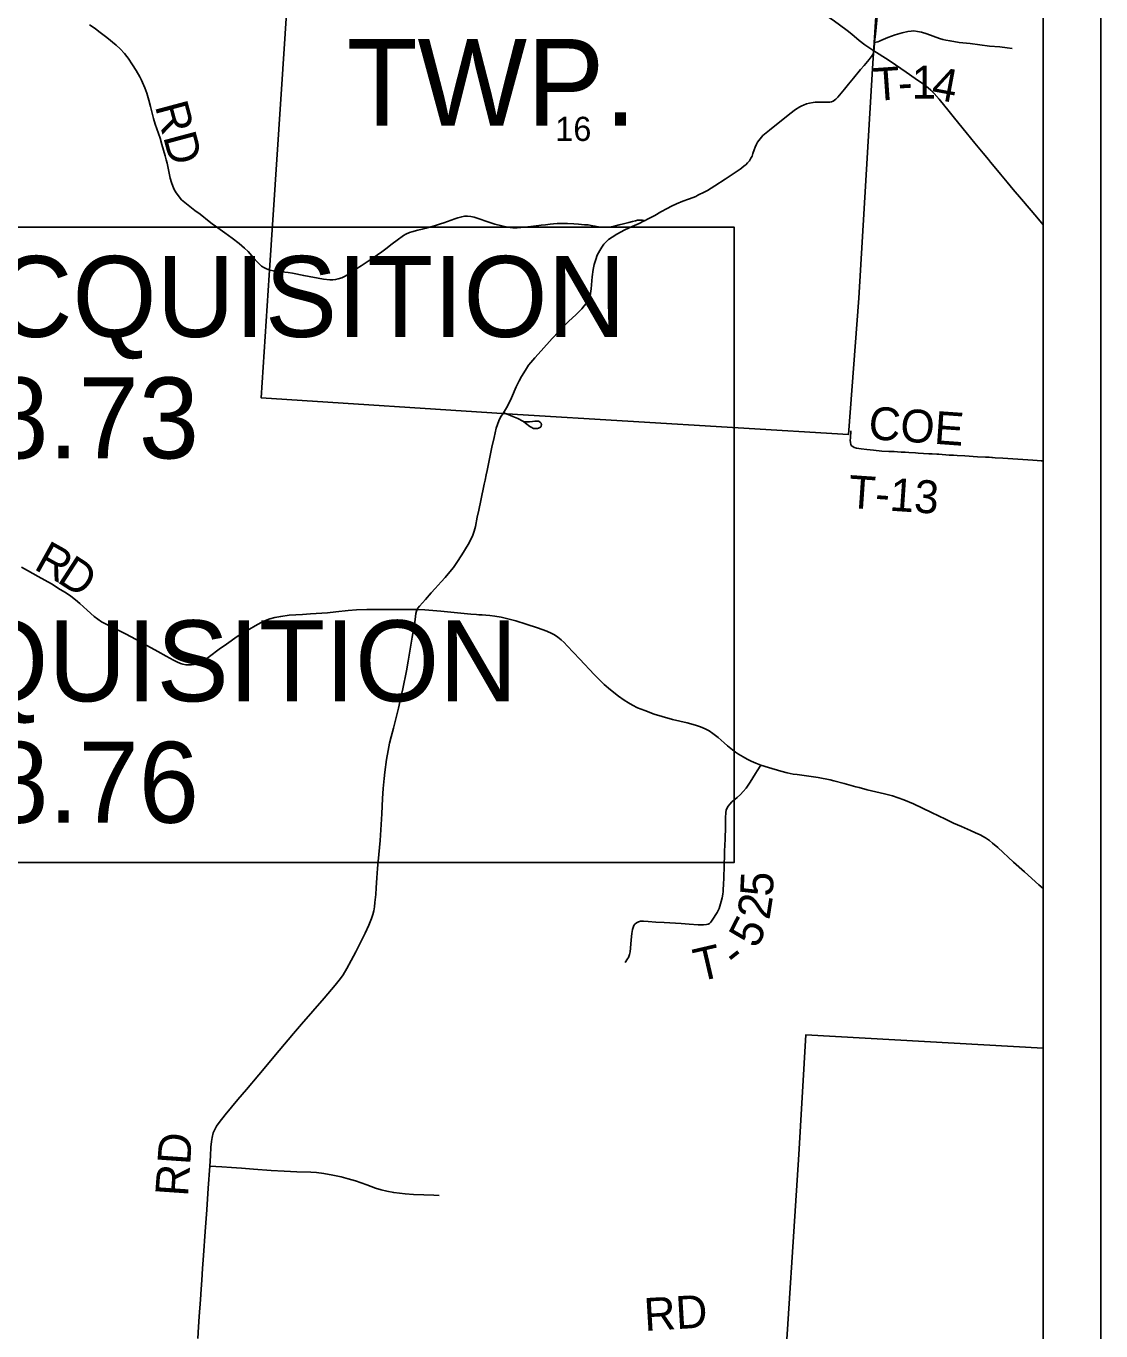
# Model space of a CAD drawing. Extents: x 0 to 34, y 0 to 22.
# Drawn here: x 7.141 to 9, y 16.952 to 19.209 of the extents above; entities that cross this region are included whole.
import ezdxf

# ---------------------------------------------------------------- set-up
doc = ezdxf.new("R2010")
doc.units = 0
for name, color, linetype in [('GM_X_Corporation', 7, 'Continuous'), ('GM_X_County_Road', 7, 'Continuous'), ('GM_X_County_Road_Text', 7, 'Continuous'), ('GM_X_Section_Text', 7, 'Continuous'), ('GM_X_State_Route', 7, 'Continuous'), ('GM_X_Township_Road', 7, 'Continuous'), ('GM_X_Township_Road_Text', 7, 'Continuous'), ('GM_X_Township_Text', 7, 'Continuous'), ('SH_Data', 7, 'Continuous'), ('SH_Text', 7, 'Continuous')]:
    doc.layers.add(name, color=color, linetype=linetype)

msp = doc.modelspace()

# ---------------------------------------------------------------- linework, layer by layer
at = {"layer": 'GM_X_Corporation'}
for points in [[(7.6147, 19.5863), (8.6299, 19.5205), (8.6049, 19.1351), (8.5816, 18.7382), (8.5636, 18.5025), (7.9912, 18.537), (7.548, 18.5656), (7.5613, 18.7776), (7.5889, 19.1863)], [(8.9, 16.3939), (8.9, 17.4412), (8.4898, 17.4646), (8.4777, 17.2575), (8.4507, 16.8404), (8.4238, 16.4246)]]:
    msp.add_lwpolyline(points, close=True, dxfattribs=at)
at = {"layer": 'GM_X_County_Road'}
for points in [[(8.6077, 19.1703), (8.6086, 19.18), (8.6087, 19.1812), (8.61, 19.1947), (8.6135, 19.231)], [(7.465, 17.2947), (7.4676, 17.3009), (7.4705, 17.3063), (7.4749, 17.313), (7.4854, 17.3261), (7.5074, 17.3524), (7.5221, 17.3696), (7.5437, 17.3949), (7.5789, 17.4371), (7.6037, 17.4665), (7.6175, 17.4825), (7.6569, 17.528), (7.6758, 17.5504), (7.6848, 17.5618), (7.6893, 17.5682), (7.6959, 17.5791), (7.7035, 17.593), (7.7114, 17.6078), (7.719, 17.6228), (7.7275, 17.6401), (7.734, 17.6542), (7.7386, 17.6657), (7.7408, 17.6723), (7.7425, 17.679), (7.7436, 17.6857), (7.7444, 17.6931), (7.7458, 17.7071), (7.7465, 17.7185), (7.7478, 17.7356), (7.7491, 17.7522), (7.7512, 17.7764), (7.7533, 17.8003), (7.7545, 17.819), (7.7562, 17.8462), (7.7577, 17.8731), (7.7588, 17.8902), (7.7593, 17.896), (7.7602, 17.9075), (7.7614, 17.9186), (7.7645, 17.9404), (7.7672, 17.9557), (7.7698, 17.9687), (7.7725, 17.9796), (7.7764, 17.9946), (7.7813, 18.0132), (7.7852, 18.0289), (7.7883, 18.0422), (7.7928, 18.0628), (7.7988, 18.0939), (7.8019, 18.1104), (7.8062, 18.1349), (7.8091, 18.1521), (7.8117, 18.1674), (7.8123, 18.1704), (7.8142, 18.1826), (7.8155, 18.1931), (7.8162, 18.1968), (7.8173, 18.1997), (7.8188, 18.2023), (7.8217, 18.2055), (7.832, 18.2171), (7.8418, 18.2284), (7.8485, 18.2358), (7.8592, 18.2478), (7.8659, 18.2552), (7.874, 18.2646), (7.8801, 18.2724), (7.8863, 18.281), (7.8947, 18.294), (7.9057, 18.312), (7.9104, 18.3208), (7.9137, 18.3282), (7.9162, 18.3352), (7.9184, 18.3435), (7.9215, 18.3592), (7.9244, 18.3717), (7.9277, 18.3881), (7.9335, 18.4163), (7.935, 18.4236), (7.9369, 18.4327), (7.9384, 18.44), (7.9444, 18.4691), (7.9467, 18.4802), (7.9505, 18.4974), (7.9543, 18.5131), (7.9562, 18.5197), (7.9587, 18.526), (7.9618, 18.5321), (7.967, 18.5399), (7.9722, 18.5487), (7.9761, 18.556), (7.9806, 18.5656), (7.9887, 18.5846), (7.9937, 18.5953), (7.9978, 18.6028), (8.0046, 18.6138), (8.0102, 18.6222), (8.0139, 18.6271), (8.0208, 18.6349), (8.0318, 18.6473), (8.051, 18.6682), (8.0625, 18.6807), (8.0801, 18.6983), (8.0917, 18.7095), (8.1021, 18.7198), (8.1065, 18.7246), (8.11, 18.729), (8.1126, 18.733), (8.1142, 18.7356), (8.1156, 18.7391), (8.1165, 18.7421), (8.1172, 18.7459), (8.1183, 18.7545), (8.1201, 18.7751), (8.122, 18.7879), (8.1239, 18.7965), (8.1263, 18.8051), (8.1291, 18.8124), (8.1333, 18.8206), (8.1367, 18.8265), (8.1405, 18.8315), (8.1441, 18.8355), (8.1487, 18.8396), (8.1546, 18.8437), (8.1628, 18.8486), (8.1769, 18.8562), (8.1894, 18.862), (8.2016, 18.8674), (8.209, 18.871), (8.2106, 18.8718), (8.2172, 18.8752), (8.2286, 18.8813), (8.2389, 18.8874), (8.2497, 18.8934), (8.2574, 18.8974), (8.2661, 18.9014), (8.2767, 18.9056), (8.2869, 18.9093), (8.2948, 18.9123), (8.2992, 18.9141), (8.3031, 18.916), (8.3066, 18.9177), (8.3116, 18.9203), (8.3195, 18.9245), (8.3326, 18.9326), (8.35, 18.9439), (8.3729, 18.9589), (8.3762, 18.9611), (8.3786, 18.9629), (8.3833, 18.9667), (8.3857, 18.9687), (8.3889, 18.9719), (8.392, 18.9756), (8.3948, 18.9801), (8.3966, 18.9837), (8.3982, 18.988), (8.4006, 18.9948), (8.4023, 18.9993), (8.4046, 19.0046), (8.4063, 19.0077), (8.4082, 19.0106), (8.4128, 19.0165), (8.4153, 19.0192), (8.418, 19.0216), (8.4268, 19.0288), (8.4622, 19.0569), (8.472, 19.0642), (8.4791, 19.0688), (8.4828, 19.0707), (8.4855, 19.072), (8.4909, 19.0739), (8.4959, 19.0752), (8.5024, 19.0764), (8.506, 19.0768), (8.5103, 19.0771), (8.5196, 19.0768), (8.5264, 19.0767), (8.5312, 19.0772), (8.534, 19.0778), (8.5368, 19.0789), (8.5393, 19.0802), (8.5418, 19.0823), (8.545, 19.0855), (8.5566, 19.0995), (8.5634, 19.1079), (8.5722, 19.1186), (8.5843, 19.1335), (8.5906, 19.1406), (8.5992, 19.1509), (8.6043, 19.1579), (8.606, 19.1608), (8.6068, 19.163), (8.6071, 19.1656)], [(8.6071, 19.1656), (8.6076, 19.1693), (8.6077, 19.1703)], [(7.133, 18.2731), (7.1434, 18.2674), (7.1623, 18.2568), (7.185, 18.2439), (7.2004, 18.2345), (7.2092, 18.2292), (7.2184, 18.2228), (7.2269, 18.2163), (7.2341, 18.2101), (7.2468, 18.1987), (7.2589, 18.1878), (7.2653, 18.1828), (7.2715, 18.1787), (7.2786, 18.1747), (7.2936, 18.1672), (7.3131, 18.1576), (7.3317, 18.1477), (7.3512, 18.1367), (7.3692, 18.1269), (7.3832, 18.119), (7.3964, 18.1121), (7.4021, 18.1093), (7.4082, 18.1064), (7.4125, 18.1051), (7.4176, 18.1039), (7.4222, 18.1038), (7.4274, 18.1042), (7.4313, 18.1047), (7.4365, 18.1061), (7.4423, 18.1086), (7.4496, 18.1122), (7.4584, 18.1186), (7.4749, 18.1309), (7.4877, 18.1401), (7.5064, 18.1532), (7.5274, 18.166), (7.5375, 18.1717), (7.5476, 18.1772), (7.5553, 18.1809), (7.5629, 18.1836), (7.5712, 18.1857), (7.5815, 18.1877), (7.5963, 18.1897), (7.6195, 18.1914), (7.6328, 18.1921), (7.6625, 18.1942), (7.6767, 18.1956), (7.6983, 18.1979), (7.7125, 18.1991), (7.7305, 18.1997), (7.7479, 18.1998), (7.7659, 18.1998), (7.7969, 18.2), (7.8106, 18.1999), (7.8173, 18.1997)], [(7.8173, 18.1997), (7.8309, 18.199), (7.8377, 18.1985), (7.8587, 18.1966), (7.8816, 18.1944), (7.9101, 18.1918), (7.92, 18.191), (7.9243, 18.1907), (7.9299, 18.1903), (7.936, 18.1898), (7.9434, 18.1892), (7.9519, 18.1881), (7.9629, 18.1863), (7.9743, 18.1839), (7.9881, 18.1802), (8.0058, 18.1745), (8.0258, 18.1678), (8.0415, 18.1622), (8.0505, 18.1583), (8.0553, 18.1557), (8.0609, 18.1519), (8.0663, 18.1474), (8.0715, 18.1425), (8.077, 18.137), (8.0986, 18.1141), (8.1237, 18.0872), (8.1328, 18.0779), (8.141, 18.0703), (8.1518, 18.0609), (8.1655, 18.0501), (8.1756, 18.0428), (8.1829, 18.0381), (8.19, 18.0341), (8.1985, 18.03), (8.2112, 18.0249), (8.2275, 18.0189), (8.2412, 18.0147), (8.2593, 18.0098), (8.2846, 18.0036), (8.299, 18), (8.3078, 17.9971), (8.3156, 17.9936), (8.3226, 17.9897), (8.3287, 17.9856), (8.338, 17.9783), (8.3483, 17.9694), (8.3544, 17.9641), (8.3627, 17.9571), (8.3678, 17.9532), (8.3731, 17.9495), (8.3813, 17.9449), (8.3884, 17.9411), (8.3954, 17.9376), (8.4034, 17.9339), (8.4116, 17.9308), (8.4251, 17.9263), (8.4462, 17.9202), (8.4572, 17.9174), (8.4675, 17.9153), (8.4749, 17.9143), (8.4946, 17.9116), (8.5111, 17.9091), (8.5318, 17.9051), (8.5384, 17.9035), (8.5559, 17.8991), (8.5762, 17.8934), (8.5821, 17.8917), (8.596, 17.888), (8.6255, 17.8808), (8.6393, 17.8773), (8.6494, 17.8744), (8.6593, 17.8708), (8.6759, 17.8639), (8.6917, 17.8563), (8.7072, 17.8488), (8.7313, 17.8372), (8.7452, 17.8305), (8.7588, 17.8243), (8.7742, 17.8178), (8.7833, 17.8138), (8.7911, 17.81), (8.8002, 17.8049), (8.8073, 17.8001), (8.8126, 17.796), (8.8215, 17.7883), (8.8488, 17.7629), (8.8678, 17.7459), (8.8928, 17.7236), (8.9, 17.7171)], [(7.438, 16.939), (7.4394, 16.9594), (7.4407, 16.9774), (7.4429, 17.0067), (7.4441, 17.0245), (7.4453, 17.0399), (7.4465, 17.0604), (7.448, 17.0828), (7.4507, 17.1242), (7.4536, 17.1619), (7.4563, 17.1993), (7.459, 17.2374), (7.46, 17.255), (7.4607, 17.27), (7.4617, 17.2799), (7.4628, 17.287), (7.465, 17.2947)]]:
    msp.add_lwpolyline(points, dxfattribs=at)
at = {"layer": 'GM_X_State_Route'}
for points in [[(8.2752, 19.5469), (8.2893, 19.5197), (8.3007, 19.5001), (8.3098, 19.4841), (8.3173, 19.4708), (8.3249, 19.4584), (8.3332, 19.4467), (8.3405, 19.4375), (8.3589, 19.4148), (8.3726, 19.398), (8.3877, 19.3798), (8.4162, 19.3436), (8.4404, 19.3134), (8.4591, 19.2914), (8.4714, 19.2774), (8.4828, 19.2642), (8.4903, 19.2559), (8.4973, 19.2488), (8.5042, 19.2425), (8.5109, 19.237), (8.5199, 19.2304), (8.5393, 19.2168), (8.5589, 19.2027), (8.5612, 19.2008)], [(8.5612, 19.2008), (8.569, 19.1946), (8.5819, 19.1838), (8.5918, 19.1762), (8.6071, 19.1656), (8.6318, 19.1499), (8.6448, 19.1414), (8.6633, 19.129), (8.6789, 19.1181), (8.693, 19.1082), (8.701, 19.102), (8.7056, 19.0979), (8.7116, 19.0917), (8.7201, 19.0819), (8.7373, 19.0606), (8.7467, 19.0491), (8.7667, 19.0245), (8.7817, 19.0063), (8.7964, 18.9886), (8.8055, 18.9776), (8.8091, 18.9733), (8.8154, 18.9656), (8.8265, 18.9523), (8.8381, 18.9385), (8.8483, 18.926), (8.8629, 18.909), (8.889, 18.8781), (8.9, 18.8651)]]:
    msp.add_lwpolyline(points, dxfattribs=at)
at = {"layer": 'GM_X_Township_Road'}
for points in [[(7.251, 19.2105), (7.2606, 19.2042), (7.2671, 19.1994), (7.2809, 19.1888), (7.2871, 19.1837), (7.2905, 19.1809), (7.2972, 19.1753), (7.3041, 19.1691), (7.3112, 19.1613), (7.3155, 19.156), (7.3178, 19.153), (7.3255, 19.1418), (7.3317, 19.1318), (7.3378, 19.1209), (7.3409, 19.1148), (7.3428, 19.1109), (7.3466, 19.1017), (7.3483, 19.0971), (7.3498, 19.0924), (7.3532, 19.0805), (7.3561, 19.0697), (7.3617, 19.0487), (7.3645, 19.0392), (7.3729, 19.0145), (7.3762, 19.0038), (7.3817, 18.9841), (7.3835, 18.9775), (7.385, 18.9715), (7.3888, 18.954), (7.3906, 18.9455), (7.3926, 18.9383), (7.395, 18.9319), (7.3975, 18.926), (7.4009, 18.92), (7.4045, 18.9148), (7.4075, 18.911), (7.4101, 18.9083), (7.4129, 18.9057), (7.4241, 18.8968), (7.4332, 18.8899), (7.4423, 18.8831), (7.4576, 18.8704), (7.4631, 18.8664), (7.4687, 18.8625), (7.4851, 18.8513), (7.4977, 18.8421), (7.5099, 18.8325), (7.5192, 18.8244), (7.525, 18.8188), (7.5375, 18.8042), (7.5452, 18.7962), (7.5484, 18.7933), (7.5521, 18.791), (7.5571, 18.7886), (7.563, 18.7866), (7.569, 18.7853), (7.5777, 18.7841), (7.5885, 18.7833), (7.5945, 18.7827), (7.6019, 18.7815), (7.6213, 18.7772), (7.6555, 18.7712), (7.6666, 18.7699), (7.6714, 18.7697), (7.6765, 18.7702), (7.6807, 18.7714), (7.6872, 18.7734), (7.6917, 18.7757), (7.6972, 18.7786), (7.7023, 18.782), (7.706, 18.7844), (7.7126, 18.7889), (7.7177, 18.7923), (7.7204, 18.794), (7.7276, 18.7987), (7.7327, 18.8021), (7.7414, 18.8079), (7.7563, 18.8183), (7.7636, 18.8236), (7.7744, 18.832), (7.7829, 18.8386), (7.7937, 18.8465), (7.7979, 18.8489), (7.8044, 18.8516), (7.8084, 18.853), (7.8186, 18.8558), (7.8263, 18.8572), (7.833, 18.8589), (7.8412, 18.8613), (7.8473, 18.8631), (7.8526, 18.8646), (7.8581, 18.8666), (7.8639, 18.8686), (7.8763, 18.8728), (7.8827, 18.875), (7.8844, 18.8756), (7.8877, 18.8768), (7.8947, 18.8788), (7.8996, 18.8797), (7.9045, 18.8799), (7.9101, 18.8795), (7.9162, 18.8782), (7.925, 18.8751), (7.9379, 18.8706), (7.9521, 18.8661), (7.9641, 18.863), (7.9739, 18.861), (7.9831, 18.8598), (7.9905, 18.8596), (7.9967, 18.86), (8.0029, 18.8606), (8.014, 18.8619), (8.0281, 18.8637), (8.032, 18.8642), (8.0394, 18.8648), (8.0474, 18.8658), (8.0535, 18.8667), (8.0597, 18.8672), (8.0676, 18.8672), (8.0773, 18.8671), (8.0885, 18.8666), (8.0968, 18.8659), (8.1071, 18.8651), (8.1135, 18.8646), (8.1182, 18.864), (8.1249, 18.8627), (8.1312, 18.8614), (8.1398, 18.8607), (8.1472, 18.8609), (8.1533, 18.8616), (8.1581, 18.8624), (8.1669, 18.8646), (8.1741, 18.8665), (8.1791, 18.8679), (8.1835, 18.8691), (8.1897, 18.8707), (8.1949, 18.872), (8.1987, 18.8728), (8.203, 18.8732), (8.207, 18.8731), (8.2095, 18.8722), (8.2106, 18.8718)], [(8.6086, 19.18), (8.6144, 19.1813), (8.6171, 19.1822), (8.6195, 19.1834), (8.6316, 19.1888), (8.6439, 19.1932), (8.6564, 19.197), (8.6661, 19.1993), (8.6716, 19.2), (8.6766, 19.2001), (8.6827, 19.1994), (8.69, 19.1978), (8.6989, 19.195), (8.7211, 19.1873), (8.7265, 19.1856), (8.732, 19.1842), (8.7393, 19.1828), (8.7547, 19.1803), (8.7741, 19.1782), (8.8076, 19.1741), (8.8251, 19.1724), (8.8377, 19.171), (8.8463, 19.1697)], [(7.967, 18.5399), (7.975, 18.5369), (7.9829, 18.5337), (7.9917, 18.5299), (8, 18.5256), (8.0022, 18.5242), (8.0051, 18.5221), (8.0124, 18.5164), (8.0161, 18.5142), (8.0175, 18.5135), (8.019, 18.513), (8.0203, 18.5127), (8.0214, 18.5126), (8.0235, 18.5125), (8.0255, 18.5127), (8.0274, 18.5132), (8.0288, 18.5137), (8.0299, 18.5143), (8.0308, 18.515), (8.0312, 18.5157), (8.0318, 18.5166), (8.0322, 18.5177), (8.0323, 18.5186), (8.0323, 18.5199), (8.0322, 18.5206), (8.0317, 18.5219), (8.031, 18.5229), (8.03, 18.5239), (8.0292, 18.5245), (8.0285, 18.5249), (8.0275, 18.5252), (8.0268, 18.5254), (8.0258, 18.5255), (8.0242, 18.5255), (8.0213, 18.5252), (8.0172, 18.5247), (8.0117, 18.5243), (8.0073, 18.5242), (8.005, 18.5244), (8.0019, 18.5247)], [(8.5673, 18.5085), (8.5667, 18.496), (8.5665, 18.4924), (8.5667, 18.4884), (8.5673, 18.4849), (8.5685, 18.4829), (8.5707, 18.4814), (8.5733, 18.4799), (8.5775, 18.4786), (8.5855, 18.4775), (8.5954, 18.4764), (8.6065, 18.4751), (8.6212, 18.4738), (8.6333, 18.4732), (8.6425, 18.4727), (8.6485, 18.4725), (8.6546, 18.472), (8.6613, 18.4717), (8.668, 18.4712), (8.6791, 18.4706), (8.684, 18.4702), (8.7025, 18.4691), (8.708, 18.4689), (8.716, 18.4683), (8.7198, 18.4681), (8.7377, 18.4669), (8.7452, 18.4665), (8.7514, 18.4661), (8.7644, 18.4654), (8.7867, 18.464), (8.8003, 18.4632), (8.8065, 18.4629), (8.8114, 18.4626), (8.8126, 18.4625), (8.8169, 18.4622), (8.8303, 18.4613), (8.8562, 18.4596), (8.8823, 18.4579), (8.8897, 18.4575), (8.8965, 18.4569), (8.9, 18.4567)], [(8.1773, 17.5893), (8.1815, 17.5956), (8.1829, 17.5983), (8.1847, 17.603), (8.1859, 17.6078), (8.1867, 17.6139), (8.1878, 17.6288), (8.1888, 17.6394), (8.1902, 17.6467), (8.191, 17.6501), (8.1921, 17.6531), (8.1942, 17.6558), (8.1967, 17.658), (8.2002, 17.6598), (8.2035, 17.6609), (8.2088, 17.6609), (8.2169, 17.6605), (8.2305, 17.6593), (8.2448, 17.6584), (8.2739, 17.6567), (8.2881, 17.6558), (8.3036, 17.6548), (8.3129, 17.6546), (8.3179, 17.655), (8.3208, 17.6558), (8.323, 17.657), (8.3253, 17.6591), (8.3279, 17.6626), (8.3362, 17.6757), (8.3396, 17.683), (8.341, 17.6866), (8.3424, 17.6907), (8.3435, 17.695), (8.3449, 17.7014), (8.346, 17.7078), (8.3465, 17.7121), (8.3467, 17.7152), (8.3472, 17.7246), (8.3477, 17.735), (8.3482, 17.7569), (8.3489, 17.7758), (8.349, 17.782), (8.35, 17.8028), (8.3505, 17.8241), (8.3509, 17.8395), (8.3514, 17.849), (8.3519, 17.8527), (8.3534, 17.8567), (8.3553, 17.8599), (8.358, 17.8633), (8.362, 17.8673), (8.371, 17.8749), (8.3766, 17.8798), (8.3813, 17.8848), (8.3863, 17.8911), (8.3932, 17.9014), (8.4025, 17.9162), (8.4055, 17.921), (8.4116, 17.9308)], [(7.459, 17.2374), (7.4798, 17.2361), (7.4965, 17.2349), (7.5138, 17.2337), (7.5343, 17.2322), (7.5652, 17.23), (7.5875, 17.2287), (7.6092, 17.2276), (7.6334, 17.2268), (7.6433, 17.226), (7.6562, 17.2244), (7.6715, 17.2218), (7.6861, 17.2188), (7.6981, 17.2156), (7.7106, 17.2117), (7.7305, 17.2047), (7.7457, 17.1993), (7.7552, 17.1964), (7.7648, 17.1941), (7.777, 17.1917), (7.7967, 17.1892), (7.8109, 17.188), (7.8289, 17.1875), (7.8463, 17.1872), (7.8557, 17.1867)]]:
    msp.add_lwpolyline(points, dxfattribs=at)
at = {"layer": 'SH_Data'}
for p, q in [((9, 21), (9, 14)), ((8.9, 20.9), (8.9, 14.1))]:
    msp.add_line(p, q, dxfattribs=at)
at = {"layer": 'SH_Text'}
for points in [[(8.3656, 18.861), (6.2897, 18.861), (6.2897, 17.7622), (8.3656, 17.7622)], [(6.2897, 18.861), (8.3656, 18.861), (8.3656, 17.7622), (6.2897, 17.7622)]]:
    msp.add_lwpolyline(points, close=True, dxfattribs=at)

# ---------------------------------------------------------------- texts
at = {"layer": 'GM_X_County_Road_Text'}
for s, height, rotation, p in [('R', 0.0568, 330.9067, (7.1527, 18.2706)), ('D', 0.0568, 327.0323, (7.1927, 18.2484)), ('RD', 0.05682, 86.0551, (7.4211, 17.1838))]:
    msp.add_text(s, height=height, rotation=rotation, dxfattribs=at).set_placement(p)
at = {"layer": 'GM_X_Section_Text'}
msp.add_text('16', height=0.04186, rotation=0, dxfattribs=at).set_placement((8.0565, 19.0099))
at = {"layer": 'GM_X_Township_Road_Text'}
for s, height, rotation, p in [('T', 0.0568, 4.0102, (8.6081, 19.0789)), ('1', 0.0568, 359.8751, (8.6727, 19.0832)), ('4', 0.0568, 349.3749, (8.7049, 19.0834)), ('-', 0.0568, 3.2019, (8.6502, 19.0819)), ('RD', 0.05682, 284.9947, (7.3637, 19.0703)), ('COE', 0.05682, 355.8896, (8.5968, 18.4946)), ('T-13', 0.05682, 356.1149, (8.5619, 18.3756)), ('5', 0.0568, 87.2059, (8.4325, 17.7028)), ('2', 0.0568, 81.2463, (8.4266, 17.6618)), ('5', 0.0568, 62.7035, (8.4043, 17.6118)), ('T', 0.0568, 13.1059, (8.3036, 17.5558)), ('-', 0.0568, 38.2385, (8.3693, 17.5771)), ('RD', 0.05682, 3.4534, (8.2114, 16.9521))]:
    msp.add_text(s, height=height, rotation=rotation, dxfattribs=at).set_placement(p)
at = {"layer": 'GM_X_Township_Text'}
msp.add_text('TWP.', height=0.15, rotation=0, dxfattribs=at).set_placement((7.6956, 19.0361))
at = {"layer": 'SH_Text'}
for s, p in [('BEGIN ACQUISITION', (6.3267, 18.671)), ('S.L.M.  28.73', (6.3267, 18.461)), ('END ACQUISITION', (6.3267, 18.041)), ('S.L.M.  28.76', (6.3267, 17.831))]:
    msp.add_text(s, height=0.14, dxfattribs=at).set_placement(p)

doc.saveas('drawing.dxf')
